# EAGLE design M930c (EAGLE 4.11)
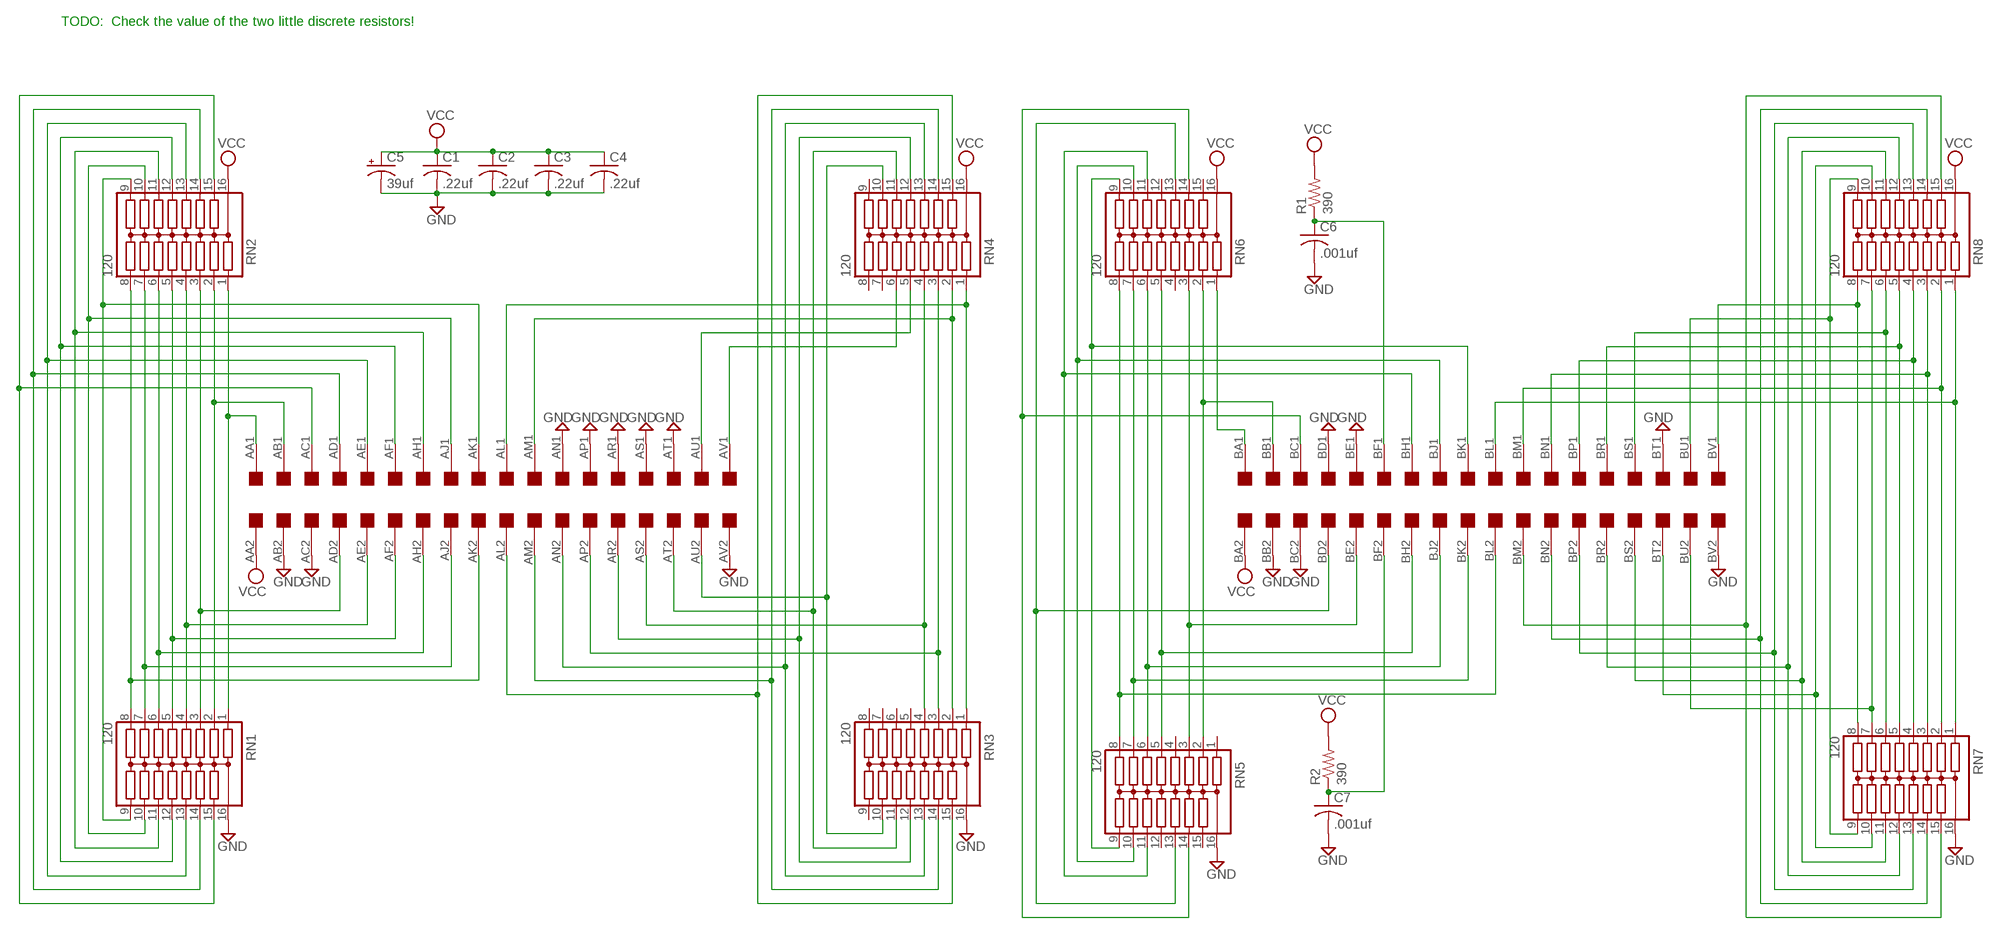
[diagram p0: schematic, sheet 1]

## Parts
C1  .22uf  C-US050-025X075  [C050-025X075]
C2  .22uf  C-US050-025X075  [C050-025X075]
C3  .22uf  C-US050-025X075  [C050-025X075]
C4  .22uf  C-US050-025X075  [C050-025X075]
C5  39uf  CPOL-USE15-5AXIAL  [E15-5]
C6  .001uf  C-US050-025X075  [C050-025X075]
C7  .001uf  C-US050-025X075  [C050-025X075]
R1  390  R-US_0207/10  [0207/10]
R2  390  R-US_0207/10  [0207/10]
RN1  120  15R  [DIL16]
RN2  120  15R  [DIL16]
RN3  120  15R  [DIL16]
RN4  120  15R  [DIL16]
RN5  120  15R  [DIL16]
RN6  120  15R  [DIL16]
RN7  120  15R  [DIL16]
RN8  120  15R  [DIL16]
U$1  DOUBLE  [EDGE-CON4]

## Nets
AA1: RN1.1 RN2.1 U$1.AA1
AB1: RN1.2 RN2.2 U$1.AB1
AC1: RN1.15 RN2.15 U$1.AC1
AD1: RN1.14 RN2.14 U$1.AD1
AD2: RN1.3 RN2.3 U$1.AD2
AE1: RN1.13 RN2.13 U$1.AE1
AE2: RN1.4 RN2.4 U$1.AE2
AF1: RN1.12 RN2.12 U$1.AF1
AF2: RN1.5 RN2.5 U$1.AF2
AH1: RN1.11 RN2.11 U$1.AH1
AH2: RN1.6 RN2.6 U$1.AH2
AJ1: RN1.10 RN2.10 U$1.AJ1
AJ2: RN1.7 RN2.7 U$1.AJ2
AK1: RN1.9 RN2.9 U$1.AK1
AK2: RN1.8 RN2.8 U$1.AK2
AL1: RN3.1 RN4.1 U$1.AL1
AL2: RN3.15 RN4.15 U$1.AL2
AM1: RN3.2 RN4.2 U$1.AM1
AM2: RN3.14 RN4.14 U$1.AM2
AN2: RN3.13 RN4.13 U$1.AN2
AP2: RN3.3 RN4.3 U$1.AP2
AR2: RN3.12 RN4.12 U$1.AR2
AS2: RN3.4 RN4.4 U$1.AS2
AT2: RN3.11 RN4.11 U$1.AT2
AU1: RN4.5 U$1.AU1
AU2: RN3.10 RN4.10 U$1.AU2
AV1: RN4.6 U$1.AV1
BA1: RN6.1 U$1.BA1
BB1: RN5.2 RN6.2 U$1.BB1
BC1: RN5.14 RN6.14 U$1.BC1
BD2: RN5.13 RN6.13 U$1.BD2
BE2: RN5.3 RN6.3 U$1.BE2
BH1: RN5.11 RN6.11 U$1.BH1
BH2: RN5.5 RN6.5 U$1.BH2
BJ1: RN5.10 RN6.10 U$1.BJ1
BJ2: RN5.6 RN6.6 U$1.BJ2
BK1: RN5.9 RN6.9 U$1.BK1
BK2: RN5.7 RN6.7 U$1.BK2
BL1: RN7.1 RN8.1 U$1.BL1
BL2: RN5.8 RN6.8 U$1.BL2
BM1: RN7.2 RN8.2 U$1.BM1
BM2: RN7.15 RN8.15 U$1.BM2
BN1: RN7.3 RN8.3 U$1.BN1
BN2: RN7.14 RN8.14 U$1.BN2
BP1: RN7.4 RN8.4 U$1.BP1
BP2: RN7.13 RN8.13 U$1.BP2
BR1: RN7.5 RN8.5 U$1.BR1
BR2: RN7.12 RN8.12 U$1.BR2
BS1: RN7.6 RN8.6 U$1.BS1
BS2: RN7.11 RN8.11 U$1.BS2
BT2: RN7.10 RN8.10 U$1.BT2
BU1: RN7.9 RN8.9 U$1.BU1
BU2: RN7.7 RN8.7 U$1.BU2
BV1: RN7.8 RN8.8 U$1.BV1
GND: C1.2 C2.2 C3.2 C4.2 C5.- C6.2 C7.2 RN1.16 RN3.16 RN5.16 RN7.16 U$1.AB2 U$1.AC2 U$1.AN1 U$1.AP1 U$1.AR1 U$1.AS1 U$1.AT1 U$1.AV2 U$1.BB2 U$1.BC2 U$1.BD1 U$1.BE1 U$1.BT1 U$1.BV2
N$1: C7.1 R2.1 U$1.BF2
N$2: C6.1 R1.1 U$1.BF1
VCC: C1.1 C2.1 C3.1 C4.1 C5.+ R1.2 R2.2 RN2.16 RN4.16 RN6.16 RN8.16 U$1.AA2 U$1.BA2
Unconnected: RN3.5 RN3.6 RN3.7 RN3.8 RN3.9 RN4.7 RN4.8 RN4.9 RN5.1 RN5.4 RN5.12 RN5.15 RN6.4 RN6.12 RN6.15

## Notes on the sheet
- TODO:  Check the value of the two little discrete resistors!

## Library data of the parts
C1-C4 C6 C7 = rcl:C-US: CAPACITOR, American symbol
C5 = rcl:CPOL-US: POLARIZED CAPACITOR, American symbol
R1 R2 = rcl:R-US_: RESISTOR, American symbol
RN1-RN8 = resistor-dil:15R: DIL RESISTOR
U$1 = dec-con:DOUBLE: Double-Height DEC board

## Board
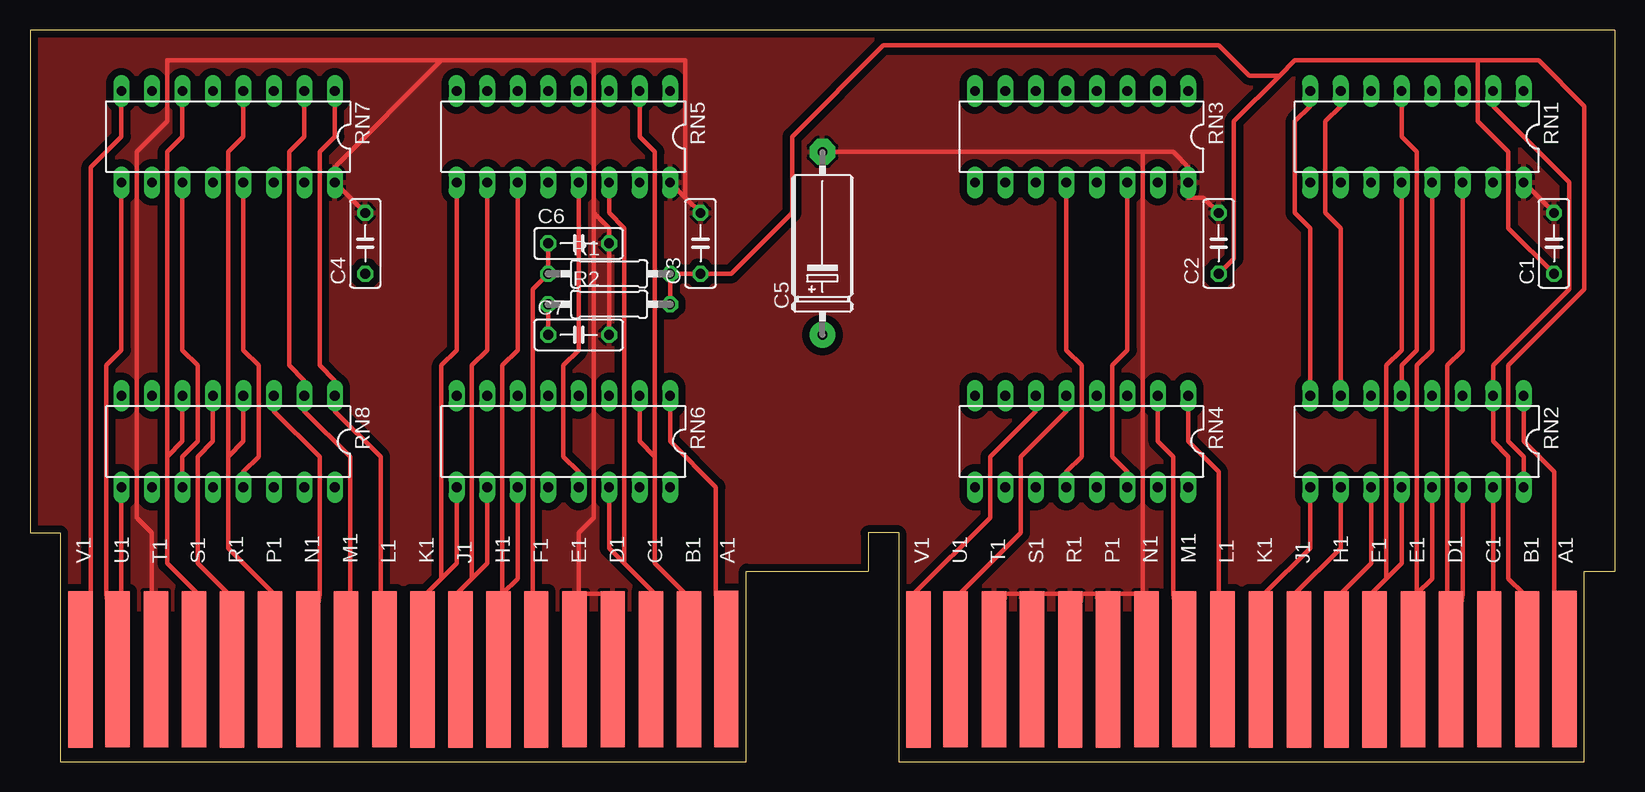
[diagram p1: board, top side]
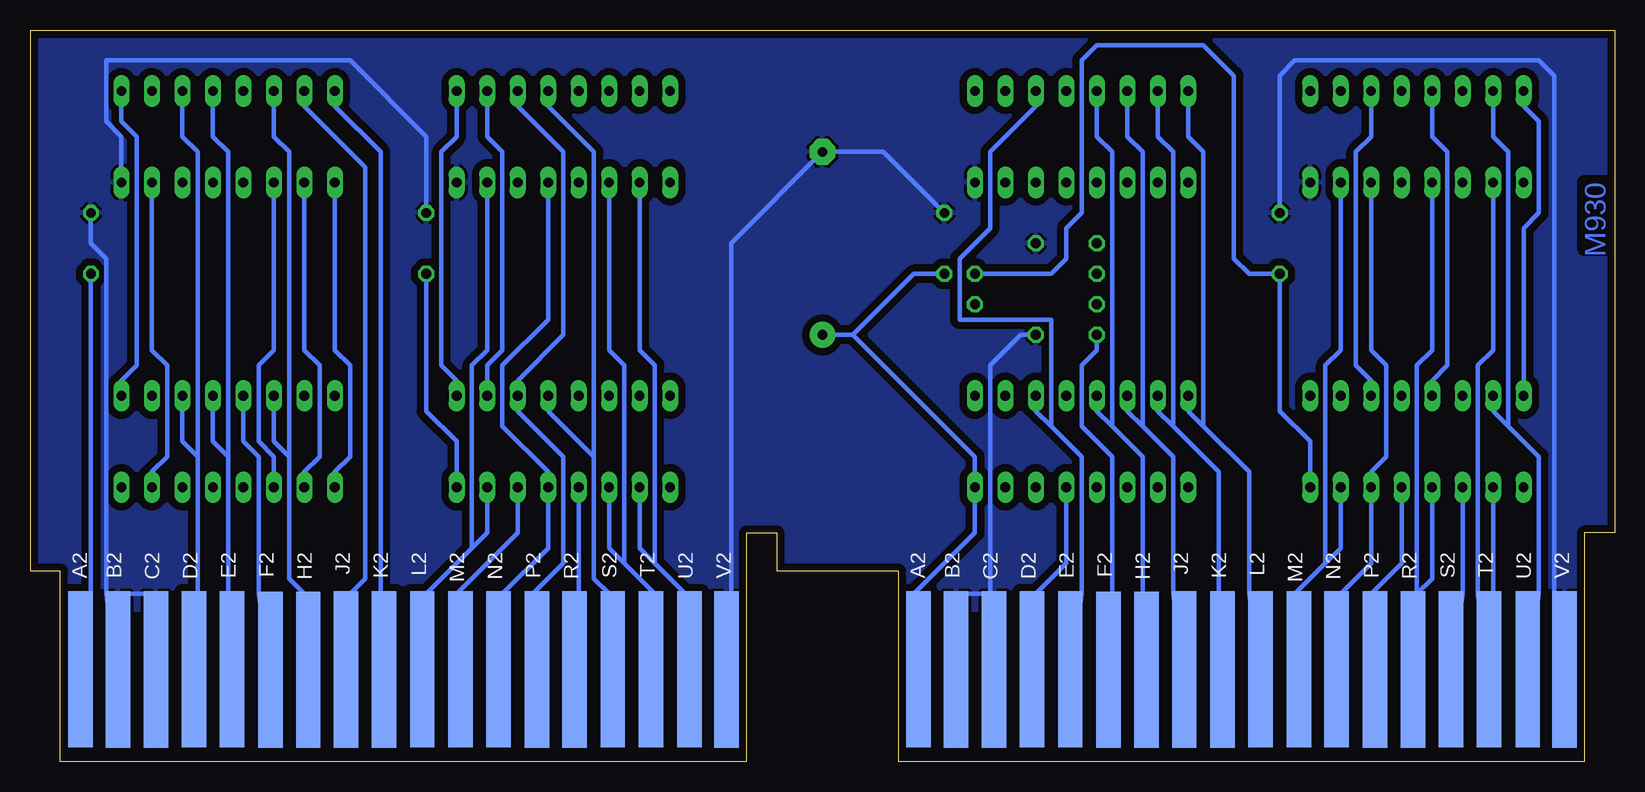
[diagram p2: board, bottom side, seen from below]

Size 132.08 x 60.96 mm. Coordinates in mm from the lower left corner, seen from the top.
Outline: 132.08,15.88 132.08,60.96 0,60.96 0,19.05
Copper layers (1*16): Top 0.035mm / dielectric 1.5mm / Bottom 0.035mm
Design rules "15mils": minimum track width 15mil, minimum drill 24mil, track to track 15mil, track to pad 10mil, pad to pad 10mil, via to via 10mil, smd to smd 10mil, copper to edge 25mil, drill to drill 10mil, minimum pad ring 10mil, minimum via ring 8mil, stop-mask expansion 0mil, vias tented up to drill 0mil, thermal gap 10mil

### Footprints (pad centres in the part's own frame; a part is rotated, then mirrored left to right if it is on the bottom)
C050-025X075 = drill 0.813 octagon: 1 -2.54,0; 2 2.54,0
E15-5 = drill 0.813 pad 2.159 round: + -7.62,0 | drill 0.813 pad 2.159 octagon: - 7.62,0
0207/10 = drill 0.813 octagon: 1 -5.08,0; 2 5.08,0
DIL16 = drill 0.813 long: 1 -8.89,-3.81; 2 -6.35,-3.81; 3 -3.81,-3.81; 4 -1.27,-3.81; 5 1.27,-3.81; 6 3.81,-3.81; 7 6.35,-3.81; 8 8.89,-3.81; 9 8.89,3.81; 10 6.35,3.81; 11 3.81,3.81; 12 1.27,3.81; 13 -1.27,3.81; 14 -3.81,3.81; 15 -6.35,3.81; 16 -8.89,3.81
EDGE-CON4 = smd 13.017 x 2.032: AA1 7.709,4.207; AB1 7.684,7.312; AC1 7.684,10.474; AD1 7.684,13.665; AE1 7.693,16.84; AF1 7.668,20.041; AH1 7.668,23.19; AJ1 7.668,26.34; AK1 7.668,29.515; AL1 7.693,32.69; AM1 7.693,35.89; AN1 7.693,39.04; AP1 7.668,42.24; AR1 7.668,45.39; AS1 7.693,48.565; AT1 7.693,51.74; AU1 7.693,54.94; AV1 7.668,58.026; BA1 7.709,74.057; BB1 7.684,77.162; BC1 7.684,80.324; BD1 7.684,83.515; BE1 7.693,86.69; BF1 7.668,89.891; BH1 7.668,93.04; BJ1 7.668,96.19; BK1 7.668,99.365; BL1 7.693,102.54; BM1 7.693,105.74; BN1 7.693,108.89; BP1 7.668,112.09; BR1 7.668,115.24; BS1 7.693,118.415; BT1 7.693,121.59; BU1 7.693,124.79; BV1 7.668,127.876 | smd 13.017 x 2.032 bottom: AA2 7.69,4.207; AB2 7.668,7.328; AC2 7.668,10.49; AD2 7.693,13.665; AE2 7.693,16.84; AF2 7.642,20.041; AH2 7.642,23.19; AJ2 7.668,26.34; AK2 7.668,29.515; AL2 7.693,32.69; AM2 7.693,35.89; AN2 7.693,39.04; AP2 7.668,42.24; AR2 7.668,45.39; AS2 7.693,48.565; AT2 7.693,51.74; AU2 7.693,54.966; AV2 7.668,58.026; BA2 7.69,74.057; BB2 7.668,77.178; BC2 7.668,80.34; BD2 7.693,83.515; BE2 7.693,86.69; BF2 7.642,89.891; BH2 7.642,93.04; BJ2 7.668,96.19; BK2 7.668,99.365; BL2 7.693,102.54; BM2 7.693,105.74; BN2 7.693,108.89; BP2 7.668,112.09; BR2 7.668,115.24; BS2 7.693,118.415; BT2 7.693,121.59; BU2 7.693,124.816; BV2 7.668,127.876

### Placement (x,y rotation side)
C1  127,43.18 90 top
C2  99.06,43.18 90 top
C3  55.88,43.18 90 top
C4  27.94,43.18 90 top
C5  66.04,43.18 90 top
C6  45.72,43.18 0 top
C7  45.72,35.56 0 top
R1  48.26,40.64 0 top
R2  48.26,38.1 0 top
RN1  115.57,52.07 180 top
RN2  115.57,26.67 180 top
RN3  87.63,52.07 180 top
RN4  87.63,26.67 180 top
RN5  44.45,52.07 180 top
RN6  44.45,26.67 180 top
RN7  16.51,52.07 180 top
RN8  16.51,26.67 180 top
U$1  132.08,0 90 top

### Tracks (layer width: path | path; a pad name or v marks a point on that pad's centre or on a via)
AA1
  Top 0.381: RN2.1 124.46,29.21 124.46,26.67 127,24.13 127,13.97 U$1.AA1
  Bottom 0.381: RN1.1 124.46,54.61 124.46,53.34 123.19,52.07 123.19,33.02 124.46,31.75 RN2.1
AB1
  Top 0.381: U$1.AB1 124.46,13.97 123.19,15.24 123.19,25.4 121.92,26.67 121.92,29.21 RN2.2 121.92,31.75 121.92,33.02 128.27,39.37 128.27,48.26 121.92,54.61 RN1.2
AC1
  Top 0.381: RN2.15 121.92,21.59 121.92,13.97 U$1.AC1
  Bottom 0.381: RN1.15 121.92,46.99 121.92,34.29 120.65,33.02 120.65,25.4 121.92,24.13 RN2.15
AD1
  Top 0.381: RN2.14 119.38,21.59 119.38,13.97 U$1.AD1 118.11,13.97 118.11,33.02 119.38,34.29 119.38,46.99 RN1.14
AD2
  Bottom 0.381: 118.11,25.4 119.38,26.67 119.38,29.21 RN2.3 | 118.11,25.4 118.11,13.97 U$1.AD2 | 118.11,25.4 118.11,50.8 119.38,52.07 119.38,54.61 RN1.3
AE1
  Top 0.381: 115.57,13.97 116.84,15.24 116.84,21.59 RN2.13 | 115.57,13.97 U$1.AE1 115.57,13.97 | 115.57,13.97 115.57,33.02 116.84,34.29 116.84,46.99 RN1.13
AE2
  Bottom 0.381: 115.57,25.4 116.84,26.67 116.84,29.21 RN2.4 | 115.57,25.4 115.57,13.97 U$1.AE2 | 115.57,25.4 115.57,50.8 116.84,52.07 116.84,54.61 RN1.4
AF1
  Top 0.381: 113.03,15.24 111.76,13.97 U$1.AF1 | 113.03,15.24 114.3,16.51 114.3,21.59 RN2.12 | 113.03,15.24 113.03,33.02 114.3,34.29 114.3,46.99 RN1.12
AF2
  Top 0.381: RN1.5 114.3,54.61 114.3,52.07 115.57,50.8 115.57,34.29 114.3,33.02 114.3,31.75 RN2.5
  Bottom 0.381: RN2.5 114.3,29.21 114.3,26.67 113.03,25.4 113.03,13.97 U$1.AF2
AH1
  Top 0.381: RN2.11 111.76,21.59 111.76,16.51 109.22,13.97 U$1.AH1
  Bottom 0.381: RN1.11 111.76,46.99 111.76,34.29 113.03,33.02 113.03,26.67 111.76,25.4 111.76,24.13 RN2.11
AH2
  Bottom 0.381: 110.49,25.4 111.76,26.67 111.76,29.21 RN2.6 | 110.49,25.4 110.49,15.24 109.22,13.97 U$1.AH2 | 110.49,25.4 110.49,50.8 111.76,52.07 111.76,54.61 RN1.6
AJ1
  Top 0.381: RN2.10 109.22,21.59 109.22,17.78 105.41,13.97 U$1.AJ1
  Bottom 0.381: RN1.10 109.22,46.99 109.22,34.29 107.95,33.02 107.95,25.4 109.22,24.13 RN2.10
AJ2
  Top 0.381: RN2.7 109.22,31.75 109.22,44.45 107.95,45.72 107.95,53.34 109.22,54.61 RN1.7
  Bottom 0.381: RN1.7 109.22,54.61 104.14,49.53 104.14,15.24 105.41,13.97 U$1.AJ2
AK1
  Top 0.381: RN2.9 106.68,21.59 106.68,17.78 102.87,13.97 U$1.AK1
  Bottom 0.381: RN1.9 106.68,46.99 106.68,34.29 105.41,33.02 105.41,25.4 106.68,24.13 RN2.9
AK2
  Top 0.381: RN2.8 106.68,31.75 106.68,44.45 105.41,45.72 105.41,53.34 106.68,54.61 RN1.8
  Bottom 0.381: RN1.8 106.68,54.61 102.87,50.8 102.87,13.97 U$1.AK2
AL1
  Top 0.381: RN4.1 96.52,29.21 96.52,26.67 99.06,24.13 99.06,13.97 U$1.AL1
  Bottom 0.381: RN3.1 96.52,54.61 96.52,52.07 97.79,50.8 97.79,33.02 96.52,31.75 RN4.1
AL2
  Bottom 0.381: 95.25,17.78 99.06,13.97 U$1.AL2 | 95.25,17.78 93.98,19.05 93.98,21.59 RN4.15 | 95.25,17.78 95.25,33.02 93.98,34.29 93.98,46.99 RN3.15
AM1
  Top 0.381: RN4.2 93.98,29.21 93.98,26.67 95.25,25.4 95.25,13.97 U$1.AM1
  Bottom 0.381: RN3.2 93.98,54.61 93.98,52.07 92.71,50.8 92.71,34.29 93.98,33.02 93.98,31.75 RN4.2
AM2
  Top 0.381: RN3.14 91.44,46.99 91.44,34.29 90.17,33.02 90.17,25.4 91.44,24.13 RN4.14
  Bottom 0.381: RN4.14 91.44,21.59 91.44,19.05 96.52,13.97 U$1.AM2
AN2
  Bottom 0.381: U$1.AN2 92.71,13.97 88.9,17.78 88.9,21.59 RN4.13 88.9,24.13 92.71,27.94 92.71,33.02 88.9,36.83 88.9,46.99 RN3.13
AP2
  Bottom 0.381: U$1.AP2 90.17,13.97 87.63,16.51 87.63,25.4 91.44,29.21 RN4.3 91.44,31.75 87.63,35.56 87.63,50.8 91.44,54.61 RN3.3
AR2
  Top 0.381: RN3.12 86.36,46.99 86.36,34.29 87.63,33.02 87.63,25.4 86.36,24.13 RN4.12
  Bottom 0.381: RN4.12 86.36,21.59 86.36,13.97 U$1.AR2
AS2
  Bottom 0.381: 85.09,25.4 88.9,29.21 RN4.4 | 85.09,25.4 85.09,15.24 83.82,13.97 U$1.AS2 | 85.09,25.4 85.09,50.8 88.9,54.61 RN3.4
AT2
  Bottom 0.381: 82.55,16.51 80.01,13.97 U$1.AT2 | 82.55,16.51 83.82,17.78 83.82,21.59 RN4.11 | 82.55,16.51 82.55,33.02 83.82,34.29 83.82,46.99 RN3.11
AU1
  Top 0.381: RN4.5 86.36,29.21 82.55,25.4 82.55,19.05 77.47,13.97 U$1.AU1
AU2
  Bottom 0.381: 80.01,16.51 77.47,13.97 U$1.AU2 | 80.01,16.51 81.28,17.78 81.28,21.59 RN4.10 | 80.01,16.51 80.01,33.02 81.28,34.29 81.28,46.99 RN3.10
AV1
  Top 0.381: RN4.6 83.82,29.21 80.01,25.4 80.01,20.32 73.66,13.97 U$1.AV1
BA1
  Top 0.381: RN6.1 53.34,29.21 53.34,26.67 57.15,22.86 57.15,13.97 U$1.BA1
BB1
  Top 0.381: 52.07,25.4 50.8,26.67 50.8,29.21 RN6.2 | 52.07,25.4 52.07,16.51 54.61,13.97 U$1.BB1 | 52.07,25.4 52.07,50.8 50.8,52.07 50.8,54.61 RN5.2
BC1
  Top 0.381: 49.53,16.51 52.07,13.97 U$1.BC1 | 49.53,16.51 48.26,17.78 48.26,21.59 RN6.14 | 49.53,16.51 49.53,44.45 48.26,45.72 48.26,46.99 RN5.14
BD2
  Top 0.381: RN5.13 45.72,46.99 45.72,34.29 44.45,33.02 44.45,25.4 45.72,24.13 RN6.13
  Bottom 0.381: RN6.13 45.72,21.59 45.72,16.51 48.26,13.97 U$1.BD2
BE2
  Bottom 0.381: 46.99,27.94 44.45,25.4 44.45,13.97 U$1.BE2 | 46.99,27.94 48.26,29.21 RN6.3 | 46.99,27.94 46.99,36.83 54.61,36.83 54.61,41.91 52.07,44.45 52.07,50.8 48.26,54.61 RN5.3
BH1
  Top 0.381: 39.37,13.97 40.64,15.24 40.64,21.59 RN6.11 | 39.37,13.97 U$1.BH1 39.37,13.97 | 39.37,13.97 39.37,33.02 40.64,34.29 40.64,46.99 RN5.11
BH2
  Bottom 0.381: 41.91,27.94 39.37,25.4 39.37,13.97 U$1.BH2 | 41.91,27.94 43.18,29.21 RN6.5 | 41.91,27.94 41.91,50.8 43.18,52.07 43.18,54.61 RN5.5
BJ1
  Top 0.381: 36.83,15.24 35.56,13.97 U$1.BJ1 | 36.83,15.24 38.1,16.51 38.1,21.59 RN6.10 | 36.83,15.24 36.83,33.02 38.1,34.29 38.1,46.99 RN5.10
BJ2
  Bottom 0.381: 39.37,27.94 36.83,25.4 36.83,13.97 U$1.BJ2 | 39.37,27.94 40.64,29.21 RN6.6 | 39.37,27.94 39.37,50.8 40.64,52.07 40.64,54.61 RN5.6
BK1
  Top 0.381: 34.29,15.24 33.02,13.97 U$1.BK1 | 34.29,15.24 35.56,16.51 35.56,21.59 RN6.9 | 34.29,15.24 34.29,33.02 35.56,34.29 35.56,46.99 RN5.9
BK2
  Bottom 0.381: 36.83,27.94 33.02,24.13 33.02,13.97 U$1.BK2 | 36.83,27.94 38.1,29.21 RN6.7 | 36.83,27.94 36.83,50.8 38.1,52.07 38.1,54.61 RN5.7
BL1
  Top 0.381: U$1.BL1 29.21,13.97 29.21,25.4 25.4,29.21 RN8.1 25.4,31.75 24.13,33.02 24.13,50.8 25.4,52.07 25.4,54.61 RN7.1
BL2
  Bottom 0.381: 34.29,27.94 30.48,24.13 30.48,13.97 U$1.BL2 | 34.29,27.94 35.56,29.21 RN6.8 | 34.29,27.94 34.29,50.8 35.56,52.07 35.56,54.61 RN5.8
BM1
  Top 0.381: U$1.BM1 26.67,13.97 26.67,25.4 22.86,29.21 RN8.2 22.86,31.75 21.59,33.02 21.59,50.8 22.86,52.07 22.86,54.61 RN7.2
BM2
  Bottom 0.381: 24.13,16.51 26.67,13.97 U$1.BM2 | 24.13,16.51 22.86,17.78 22.86,21.59 RN8.15 | 24.13,16.51 24.13,33.02 22.86,34.29 22.86,46.99 RN7.15
BN1
  Top 0.381: RN8.3 20.32,29.21 24.13,25.4 24.13,13.97 U$1.BN1
  Bottom 0.381: RN7.3 20.32,54.61 20.32,52.07 21.59,50.8 21.59,33.02 20.32,31.75 RN8.3
BN2
  Bottom 0.381: U$1.BN2 22.86,13.97 20.32,16.51 20.32,21.59 RN8.14 20.32,24.13 19.05,25.4 19.05,33.02 20.32,34.29 20.32,46.99 RN7.14
BP1
  Top 0.381: 16.51,25.4 17.78,26.67 17.78,29.21 RN8.4 | 16.51,25.4 16.51,17.78 20.32,13.97 U$1.BP1 | 16.51,25.4 16.51,50.8 17.78,52.07 17.78,54.61 RN7.4
BP2
  Top 0.381: RN7.13 17.78,46.99 17.78,34.29 19.05,33.02 19.05,25.4 17.78,24.13 RN8.13
  Bottom 0.381: RN8.13 17.78,21.59 17.78,16.51 20.32,13.97 U$1.BP2
BR1
  Top 0.381: RN8.5 15.24,29.21 15.24,26.67 13.97,25.4 13.97,16.51 16.51,13.97 U$1.BR1
  Bottom 0.381: RN7.5 15.24,54.61 15.24,52.07 13.97,50.8 13.97,33.02 15.24,31.75 RN8.5
BR2
  Bottom 0.381: 16.51,13.97 15.24,15.24 15.24,21.59 RN8.12 | 16.51,13.97 U$1.BR2 16.51,13.97 | 16.51,13.97 16.51,33.02 15.24,34.29 15.24,46.99 RN7.12
BS1
  Top 0.381: 11.43,25.4 12.7,26.67 12.7,29.21 RN8.6 | 11.43,25.4 11.43,16.51 13.97,13.97 U$1.BS1 | 11.43,25.4 11.43,50.8 12.7,52.07 12.7,54.61 RN7.6
BS2
  Top 0.381: RN7.11 12.7,46.99 12.7,34.29 13.97,33.02 13.97,26.67 12.7,25.4 12.7,24.13 RN8.11
  Bottom 0.381: RN8.11 12.7,21.59 12.7,13.97 U$1.BS2
BT2
  Bottom 0.381: RN8.10 10.16,21.59 10.16,13.97 U$1.BT2 11.43,13.97 11.43,33.02 10.16,34.29 10.16,46.99 RN7.10
BU1
  Top 0.381: RN8.9 7.62,21.59 7.62,13.97 U$1.BU1 6.35,13.97 6.35,33.02 7.62,34.29 7.62,46.99 RN7.9
BU2
  Bottom 0.381: 8.89,27.94 6.35,25.4 6.35,13.97 U$1.BU2 | 8.89,27.94 10.16,29.21 RN8.7 | 8.89,27.94 8.89,50.8 10.16,52.07 10.16,54.61 RN7.7
BV1
  Top 0.381: RN7.8 7.62,54.61 7.62,52.07 5.08,49.53 5.08,13.97 U$1.BV1
  Bottom 0.381: RN8.8 7.62,31.75 7.62,44.45 6.35,45.72 6.35,53.34 7.62,54.61 RN7.8
GND
  Top 0.381: RN1.16 C1.2 | U$1.AT1 81.28,13.97 82.55,13.97 U$1.AS1 83.82,13.97 86.36,13.97 U$1.AR1 87.63,13.97 88.9,13.97 U$1.AP1 90.17,13.97 92.71,13.97 | 92.71,13.97 U$1.AN1 92.71,13.97 | 45.72,13.97 48.26,13.97 U$1.BD1 | 45.72,13.97 U$1.BE1 45.72,13.97 | C7.2 C6.2 48.26,44.45 46.99,45.72 | C2.2 97.79,46.99 96.52,46.99 RN3.16 96.52,49.53 95.25,50.8 92.71,50.8 | C4.2 RN7.16 25.4,49.53 34.29,58.42 | 54.61,46.99 RN5.16 | 54.61,46.99 C3.2 | 46.99,58.42 54.61,58.42 54.61,46.99 | 34.29,58.42 46.99,58.42 | C5.- 92.71,50.8 | 46.99,58.42 46.99,45.72 | 34.29,58.42 11.43,58.42 11.43,53.34 8.89,50.8 8.89,20.32 10.16,19.05 10.16,13.97 U$1.BT1 | 45.72,13.97 45.72,19.05 46.99,20.32 46.99,45.72 | 92.71,50.8 92.71,13.97
  Bottom 0.381: C1.2 127,43.18 125.73,41.91 125.73,13.97 U$1.AB2 124.46,13.97 121.92,13.97 U$1.AC2 | 52.07,13.97 54.61,13.97 U$1.BB2 | 52.07,13.97 U$1.BC2 52.07,13.97 | C3.2 60.96,50.8 C5.- 73.66,43.18 73.66,13.97 U$1.AV2 73.66,12.7 74.26,12.7 | C4.2 27.94,57.15 26.67,58.42 6.35,58.42 5.08,57.15 5.08,13.97 U$1.BV2 | 52.07,13.97 52.07,33.02 49.53,35.56 C7.2 | C2.2 99.06,52.07 105.41,58.42 125.73,58.42 125.73,53.34 124.46,52.07 124.46,49.53 RN1.16
  pour Bottom (isolate 0.61): 0,60.96 132.08,60.96 132.08,12.7 0,12.7
  pour Top (isolate 0.61): 0,60.96 132.08,60.96 132.08,12.7 0,12.7
N$1
  Top 0.381: C7.1 R2.1
  Bottom 0.381: C7.1 43.18,34.29 44.45,33.02 44.45,27.94 41.91,25.4 41.91,13.97 U$1.BF2
N$2
  Top 0.381: C6.1 R1.1 41.91,39.37 41.91,13.97 U$1.BF1
VCC
  Top 0.381: 120.65,58.42 105.41,58.42 104.14,57.15 | 120.65,58.42 125.73,58.42 129.54,54.61 129.54,39.37 123.19,33.02 123.19,26.67 124.46,25.4 124.46,24.13 RN2.16 | 104.14,57.15 100.33,53.34 100.33,41.91 C2.1 | C1.1 123.19,44.45 123.19,50.8 120.65,53.34 120.65,58.42 | R2.2 R1.2 C3.1 58.42,40.64 63.5,45.72 63.5,52.07 71.12,59.69 99.06,59.69 101.6,57.15 104.14,57.15
  Bottom 0.381: C1.1 127,13.97 U$1.AA2 | C2.1 99.06,29.21 96.52,26.67 96.52,24.13 RN4.16 | U$1.BA2 58.42,13.97 53.34,19.05 53.34,21.59 RN6.16 53.34,24.13 53.34,25.4 63.5,35.56 | RN8.16 25.4,24.13 25.4,26.67 27.94,29.21 C4.1 30.48,40.64 31.75,41.91 31.75,57.15 34.29,59.69 43.18,59.69 44.45,58.42 44.45,45.72 45.72,44.45 45.72,41.91 46.99,40.64 R1.2 | 63.5,35.56 C5.+ | 63.5,35.56 58.42,40.64 C3.1

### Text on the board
Bottom: M930
tValues: M930C Unibus Terminator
